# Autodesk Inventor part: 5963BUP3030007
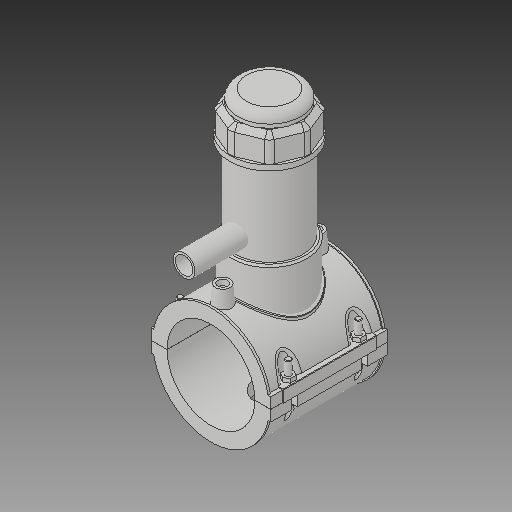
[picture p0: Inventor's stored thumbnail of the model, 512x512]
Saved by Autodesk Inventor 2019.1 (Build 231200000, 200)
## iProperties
Created: 2017-07
Part Number: 5963BUP3030007
Material: Generic
Description: PLASSON TAPPING SADDLE 3''IPS x 3/4''CTS
Document SubType Name: Modeling
Designer: KIM
Density: 1 g/cm^3
Appearance: Default
Author: KIM
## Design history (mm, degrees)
derived "5963BBP_5963BUP.ipt"
feature "Solid1::5963BBP_5963BUP.ipt"
feature "Solid2::5963BBP_5963BUP.ipt"
feature "Solid3::5963BBP_5963BUP.ipt"
tag "TaggingFeature1"
body "Solid1"
body "Solid2"
body "Solid3"
other parameters: "d0" = 88.7, "d2" = 120.904, "d3" = 22.175, "d4" = 118.11, "d5" = 0, "d6" = 0.1, "d8" = 0, "d19" = 6, "d20" = 6, "d21" = 70.866, "d23" = 0, "d24" = 35.433, "d26" = 0, "d27" = 3, "d28" = 3, "d29" = 3, "d30" = 29.56667, "d31" = 6, "d32" = 0, "d33" = 0, "d34" = 0.6, "d40" = 59.9612, "d41" = 79.83, "d43" = 0, "d45" = 0, "d47" = 128.521, "d70" = 15, "d72" = 0, "d73" = 6, "d75" = 5, "d76" = 0, "d77" = 4.435, "d78" = 74.35, "d79" = 15, "d80" = 47.244, "d82" = 5 deg, "d84" = 4, "d85" = 14, "d86" = 0, "d87" = 3, "d88" = 0, "d89" = 1, "d90" = 1, "d91" = 94.488, "d92" = 0, "d93" = 0.5, "d94" = 46.68421, "d96" = 117.6162, "d97" = 2.3622, "d98" = 0, "d102" = 0.887, "d120" = 140 deg, "d121" = 24.228, "d122" = 20 deg, "d123" = 230.62, "d124" = 69.186, "d126" = 0, "d143" = 91.361, "d145" = 20.46923, "d149" = 1.3305, "d150" = 22.51615, "d153" = 118.11, "d154" = 0, "d156" = 57.655, "d157" = 160 deg, "d159" = 5.322, "d161" = 1.3305, "d162" = 70.866, "d163" = 0, "d164" = 44.35, "d167" = 8.87, "d168" = 56.24878, "d170" = 3.2805, "d172" = 0, "d173" = 1, "d175" = 44.35, "d176" = 20 deg, "d177" = 6.209, "d178" = 26.61, "d180" = 0, "d183" = 10.644, "d184" = 4.9672, "d185" = 38.38575, "d186" = 38.38575, "d187" = 57.655, "d188" = 7.983, "d189" = 6.209, "d190" = 0, "d191" = 86.4825, "d193" = 6.9984, "d194" = 4.13385, "d195" = 90 deg, "d197" = 0, "d199" = 0, "d200" = 13.305, "d202" = 0, "d203" = 177.038, "d204" = 75.8385, "d205" = 55.881, "d206" = 67.8555, "d207" = 132.7785, "d208" = 138.08964, "d209" = 164.64534, "d210" = 68.6538, "d211" = 79.83, "d212" = 63.864, "d213" = 48.5766, "d216" = 0, "d217" = 8.87, "d218" = 8.87, "d219" = 1.774, "d222" = 88.7, "d224" = 0, "d225" = 65.024, "d226" = 22.1, "d227" = 17.68, "d228" = 86.106, "d230" = 5.322, "d_" = 88.7, "B_" = 120.904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
